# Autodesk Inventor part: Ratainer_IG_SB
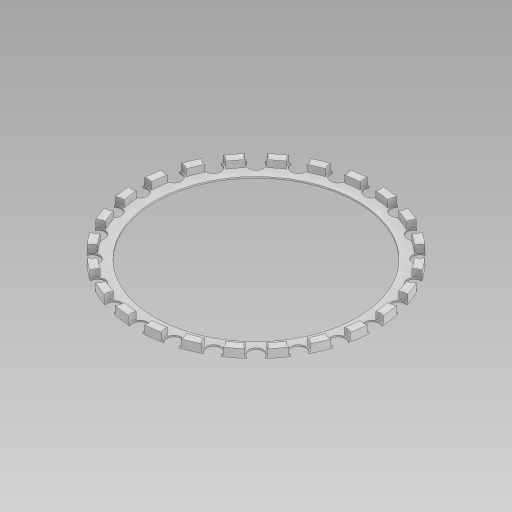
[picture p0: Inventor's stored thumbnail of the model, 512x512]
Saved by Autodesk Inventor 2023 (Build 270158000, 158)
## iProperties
Created: 2024-05
Part Number: Ratainer_IG_SB
Material: 一般
Document SubType Name: Modeling
Designer: kumagai
Density: 1 g/cm^3
Appearance: 既定
Author: kumagai
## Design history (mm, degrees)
derived "CoreSketch.ipt"
  sketch "Vertical"
    geometry: L1 (0, 65.337)-(0, -65.337) reference; L2 (-46.2, 0)-(46.2, 0) reference; L3 (-11, 2)-(11, 2) reference; L4 (11, 2)-(11, -2) reference; L5 (11, -2)-(-11, -2) reference; L6 (-11, -2)-(-11, 2) reference; L7 (11, 2)-(33, 2) reference; L8 (33, 2)-(33, -2) reference; L9 (33, -2)-(11, -2) reference; L10 (11, -2)-(11, 2) reference; L11 (22, 2.772)-(22, -2.683) reference; L12 (-33, 2)-(-11, 2) reference; L13 (-11, 2)-(-11, -2) reference; L14 (-11, -2)-(-33, -2) reference; L15 (-33, -2)-(-33, 2) reference; L16 (-22, 4.087)-(-22, -4.199) reference; L17 (-33, 10)-(-11, 10) reference; L18 (-11, 10)-(-11, 6) reference; L19 (-11, 6)-(-33, 6) reference; L20 (-33, 6)-(-33, 10) reference; L21 (-27.353, 10)-(-16.647, 10) reference; L22 (-16.647, 10)-(-16.647, 16) reference; L23 (-16.647, 16)-(-27.353, 16) reference; L24 (-27.353, 16)-(-27.353, 10) reference; L25 (11, 16)-(33, 16) reference; L26 (33, 16)-(33, 12) reference; L27 (33, 12)-(11, 12) reference; L28 (11, 12)-(11, 16) reference; L29 (16.134, 12)-(27.866, 12) reference; L30 (27.866, 12)-(27.866, 6) reference; L31 (27.866, 6)-(16.134, 6) reference; L32 (16.134, 6)-(16.134, 12) reference; L33 (-22, 18.272)-(-22, 9.031) reference; L34 (22, 22.635)-(22, 12.71) reference; L35 (33, -2)-(35, -2) reference; L36 (35, -2)-(35, 10) reference; L37 (35, 10)-(33, 10) reference; L38 (33, 10)-(33, -2) reference; L39 (0, -4)-(37.5, -4) reference; L40 (40.5, -1)-(40.5, 14) reference; L41 (43.9, -8)-(0, -8) reference; L42 (0, -4)-(0, -8) reference; L43 (35, -2)-(39, -2) reference; L44 (39, -2)-(39, 3.066) reference; L45 (38.45, 8.685)-(41.471, 10.429) reference; L46 (38.45, 10)-(35, 10) reference; L47 (40.5, 9.627)-(41.993, 8.375) reference; L48 (41.55, 3.315)-(40.5, 2.709) reference; L49 (37.5, -4)-(40.5, -1) reference; L50 (-43, 43.294)-(-1, 43.294) reference; L51 (-1, 43.294)-(-1, 26) reference; L52 (-1, 26)-(-43, 26) reference; L53 (-43, 26)-(-43, 43.294) reference; L54 (1, 43.294)-(43, 43.294) reference; L55 (43, 43.294)-(43, 26) reference; L56 (43, 26)-(1, 26) reference; L57 (1, 26)-(1, 43.294) reference; L58 (-22, 45.556)-(-22, 31.232) reference; L59 (22, 47.214)-(22, 32.287) reference; L60 (48, 5.268)-(48, -2.616) reference; L61 (43.6, -11)-(54, -11) reference; L62 (54, -11)-(54, 18) reference; L63 (45.222, -3.461)-(46.5, -2.566) reference; L64 (48, -2.616)-(49.192, -3.808) reference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; A1 r 3.1 centre (40, 6) between (39, 3.066) and (38.45, 8.685) reference; A2 r 3.1 centre (47, -6) between (45.222, -3.461) and (49.192, -3.808) reference; A3 r 3.1 centre (47, 13) between (43.9, 13) and (49, 10.631) reference; 2 further points; 1 other entity
    constraints: 1 other
sketch "スケッチ3"
  geometry: L1 (0, -67.9)-(0, 67.9) reference; L2 (-74.5, 0)-(69, 0) reference; C1 r 3 at (-47, 0); C2 r 3.5 at (-47, 0); 7 further points
  constraints: 4 coincident, 2 centre point, 2 horizontal alignment, 2 point on line, 4 other
  dimensions: "d28" = 1.96961 distance of point (-45.03, 0) point (-47, 0) (derived); "d29" = 6 diameter of C1; "d30" = 1.5 distance of point (-48.5, 0) C1.centre; "d31" = 6 distance of C1.centre point (-41, 0); "d39" = 7 diameter of C2
extrude "押し出し4" new body sketch "スケッチ3" distance "d32" = 0.6; taper "d33" = 0 deg
sketch "スケッチ5"
  geometry: L1 (0, 59.102)-(0, -24.112) reference; L2 (-62.4, 0)-(73.4, 0) reference; L3 (45.5, 0)-(48.5, 0); L4 (48.5, 0)-(48.5, 3.4); L5 (48.5, 3.4)-(45.5, 3.4); L6 (45.5, 3.4)-(45.5, 0); L7 (0, -24.112)-(0, 59.102) reference; 2 further points
  constraints: 8 end point, 2 point on line, 2 vertical, 1 horizontal
  dimensions: "d40" = 1.5 distance from line of point (47, 0) L4; "d41" = 1.5 distance from line of L6 point (47, 0); "d42" = 3.4 distance between parallel lines of L2 L5
revolve "回転1" sketch "スケッチ5" stored, may be unused: angle "d43" = 90 deg
extrude "押し出し5" cut sketch "スケッチ3" extent not by distance; stored distance "d34" = 0; taper "d35" = 0 deg
extrude "押し出し6" cut sketch "スケッチ3" stored distance "d44" = 10; taper "d45" = 0 deg
node "ソリッド2"
pattern_circular "円形状パターン2" dims angle "d37" = 360 deg
